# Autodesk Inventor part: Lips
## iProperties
Created: 2008-12
Part Number: Lips
Document SubType Name: Modeling
Designer: Ed O'Halloran
Density: 1 g/cm^3
Author: Ed O'Halloran
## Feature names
1. Extrusion1
2. Revolution1
3. Fillet1
4. Shell1
5. Fillet2
6. Extrusion4
7. Fillet3
8. Fillet4
9. Fillet7
10. Fillet8
11. Fillet9
12. Fillet10
13. Extrusion5
14. FaceDraft1
15. Fillet11
16. Chamfer1
17. FaceDraft2
18. Extrusion6
19. Fillet12
20. Shell2
